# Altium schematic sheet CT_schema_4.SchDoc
size 573 x 363 mm
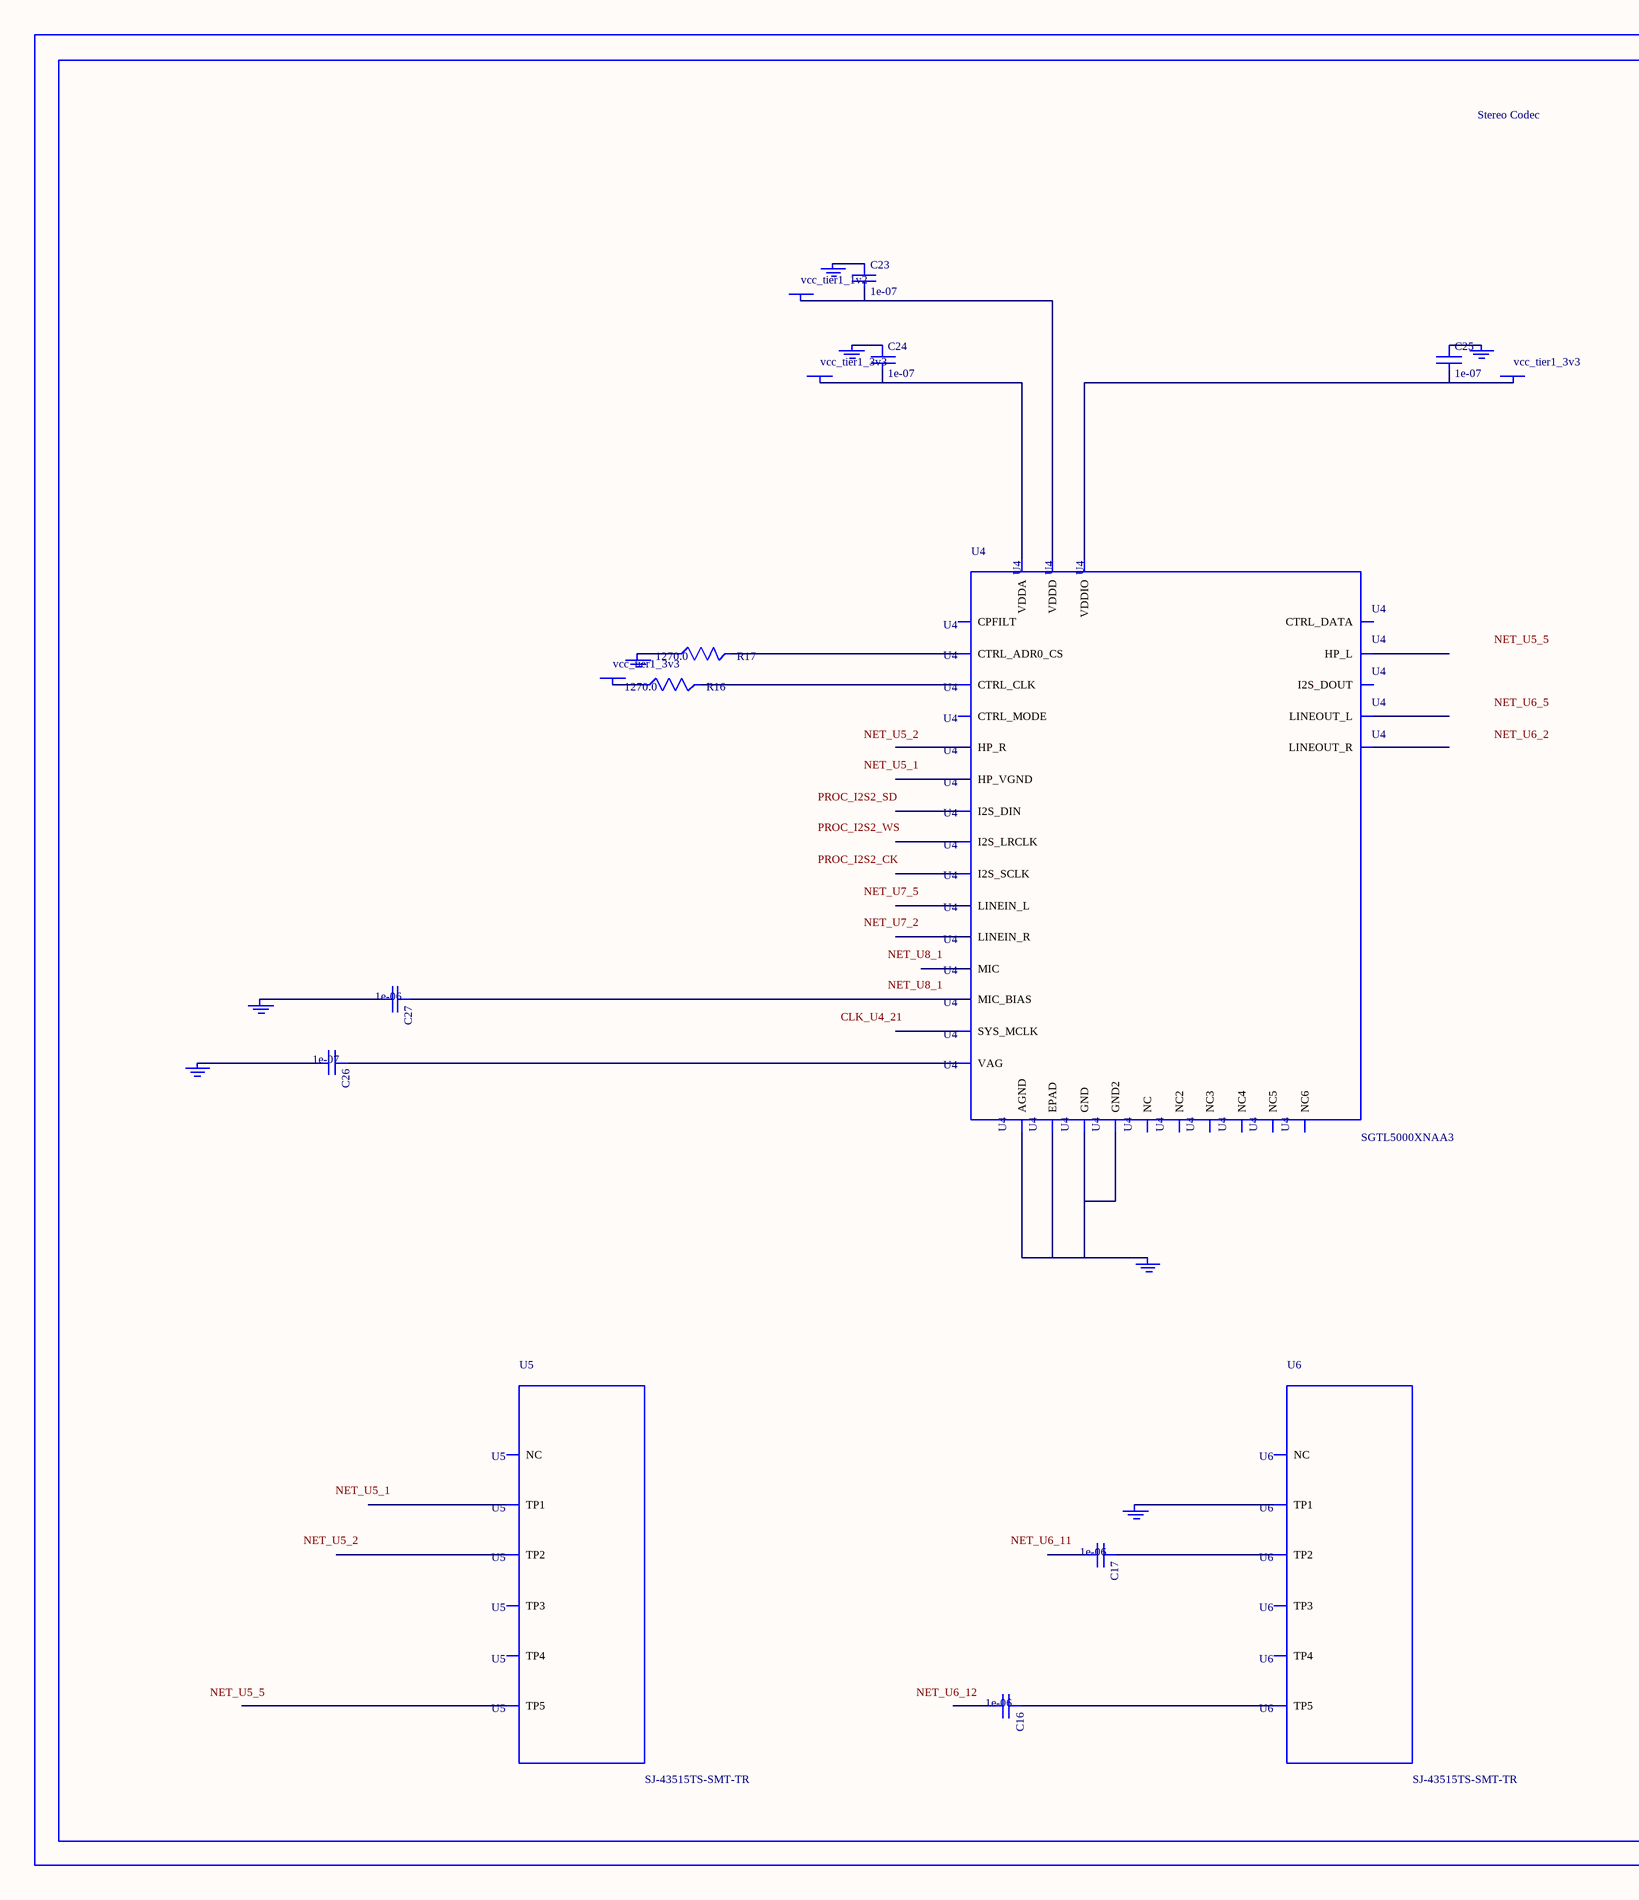
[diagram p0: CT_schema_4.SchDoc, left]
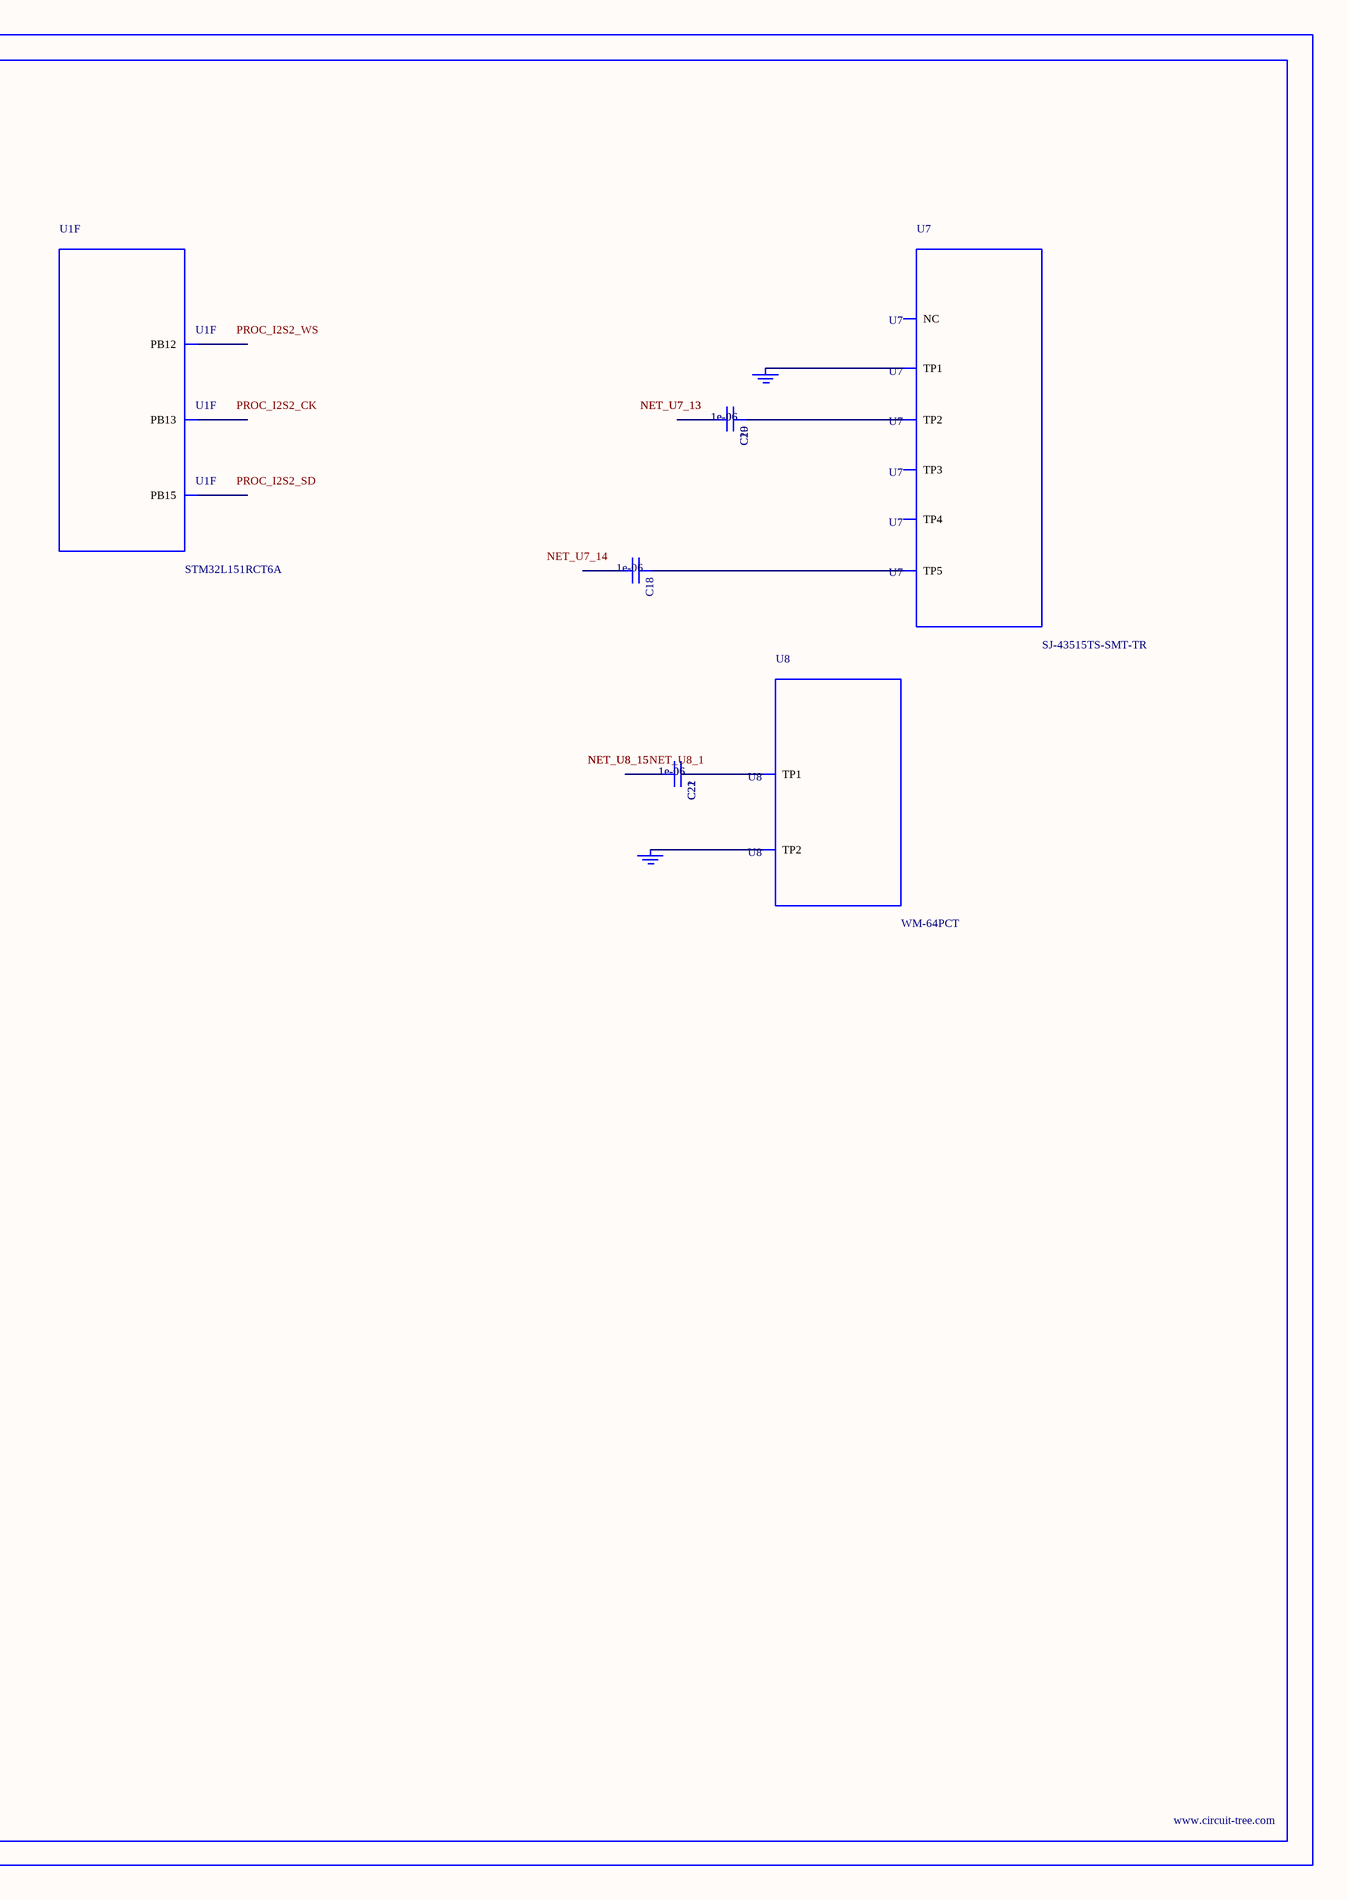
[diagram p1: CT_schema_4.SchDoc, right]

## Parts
BORDER3  (no value)
C16  1e-06  [C0603]
C17  1e-06  [C0603]
C18  1e-06  [C0603]
C19  1e-06  [C0603]
C20  1e-06  [C0603]
C21  1e-06  [C0603]
C22  1e-06  [C0603]
C23  1e-07  [C0402]
C24  1e-07  [C0402]
C25  1e-07  [C0402]
C26  1e-07  [C0402]
C27  1e-06  [C0603]
GND_INSTANCE_3_0  (no value)
GND_INSTANCE_3_1  (no value)
GND_INSTANCE_3_2  (no value)
GND_INSTANCE_3_3  (no value)
GND_INSTANCE_3_4  (no value)
GND_INSTANCE_3_5  (no value)
GND_INSTANCE_3_6  (no value)
GND_INSTANCE_3_7  (no value)
GND_INSTANCE_3_8  (no value)
GND_INSTANCE_3_9  (no value)
GND_INSTANCE_3_10  (no value)
POWER_INSTANCE_3_0  vcc_tier1_3v3
POWER_INSTANCE_3_1  vcc_tier1_3v3
POWER_INSTANCE_3_2  vcc_tier1_3v3
POWER_INSTANCE_3_3  vcc_tier1_1v2
R16  1270.0  [R0603]
R17  1270.0  [R0603]
U1  STM32L151RCT6A  [LQFP64]  (part F of 8)
U4  SGTL5000XNAA3  [QFN-32]
U5  SJ-43515TS-SMT-TR  [SJ-43515TS-SMT-TR]
U6  SJ-43515TS-SMT-TR  [SJ-43515TS-SMT-TR]
U7  SJ-43515TS-SMT-TR  [SJ-43515TS-SMT-TR]
U8  WM-64PCT  [WM-64PC]

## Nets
NetC16_1: C16.1 U6.5(TP5)
NetC17_1: C17.1 U6.2(TP2)
NetC18_1: C18.1 U7.5(TP5)
NetC19_1: C19.1 C20.1 U7.2(TP2)
NetC19_2: C19.2 C20.2
NetC21_1: C21.1 C22.1 U8.1(TP1)
NetC21_2: C21.2 C22.2
NetC23_1: C23.1 GND_INSTANCE_3_5.0(GND)
NetC23_2: C23.2 POWER_INSTANCE_3_3.0(PWR) U4.30(VDDD)
NetC24_1: C24.1 GND_INSTANCE_3_1.0(GND)
NetC24_2: C24.2 POWER_INSTANCE_3_0.0(PWR) U4.5(VDDA)
NetC25_1: C25.1 GND_INSTANCE_3_4.0(GND)
NetC25_2: C25.2 POWER_INSTANCE_3_1.0(PWR) U4.20(VDDIO)
NetC26_1: C26.1 U4.10(VAG)
NetC26_2: C26.2 GND_INSTANCE_3_2.0(GND)
NetC27_1: C27.1 U4.16(MIC_BIAS)
NetC27_2: C27.2 GND_INSTANCE_3_3.0(GND)
NetGND_INSTANCE_3_0_0: GND_INSTANCE_3_0.0(GND) U4.1(GND) U4.3(GND2) U4.7(AGND) U4.EXP(EPAD)
NetGND_INSTANCE_3_6_0: GND_INSTANCE_3_6.0(GND) R17.1
NetGND_INSTANCE_3_7_0: GND_INSTANCE_3_7.0(GND) U6.1(TP1)
NetGND_INSTANCE_3_8_0: GND_INSTANCE_3_8.0(GND) GND_INSTANCE_3_9.0(GND) U7.1(TP1)
NetGND_INSTANCE_3_10_0: GND_INSTANCE_3_10.0(GND) U8.2(TP2)
NetPOWER_INSTANCE_3_2_0: POWER_INSTANCE_3_2.0(PWR) R16.1
NetR16_2: R16.2 U4.29(CTRL_CLK)
NetR17_2: R17.2 U4.31(CTRL_ADR0_CS)

Not connected (* = marked no-connect by the designer): C16 2; C17 2; C18 2; U1 33(PB12) 34(PB13) 36(PB15); U4 2(HP_R) 4(HP_VGND) 6(HP_L) 8(NC) 9(NC2) 11(LINEOUT_R) 12(LINEOUT_L) 13(LINEIN_R) 14(LINEIN_L) 15(MIC) 17(NC3) 18(CPFILT) 19(NC4) 21(SYS_MCLK) 22(NC5) 23(I2S_LRCLK) 24(I2S_SCLK) 25(I2S_DOUT) 26(I2S_DIN) 27(CTRL_DATA) 28(NC6) 32(CTRL_MODE); U5 1(TP1) 2(TP2) 3(TP3) 4(TP4) 5(TP5) 6(NC); U6 3(TP3) 4(TP4) 6(NC); U7 3(TP3) 4(TP4) 6(NC)

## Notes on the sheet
- Labels drawn without touching a wire or pin: CLK_U4_21, NET_U5_1, NET_U5_2, NET_U5_5, NET_U6_2, NET_U6_5, NET_U6_11, NET_U6_12, NET_U7_2, NET_U7_5, NET_U7_14, NET_U8_1, PROC_I2S2_CK, PROC_I2S2_SD, PROC_I2S2_WS

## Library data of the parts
BORDER3 = BORDER_PAGE3
C16-C22 C27 = C0603C105K3RACTU
C23-C26 = C0402C104K3RACTU
GND_INSTANCE_3_0-GND_INSTANCE_3_10 = GND
POWER_INSTANCE_3_0-POWER_INSTANCE_3_3 = PWR
R16 R17 = RC0603FR-071K27L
